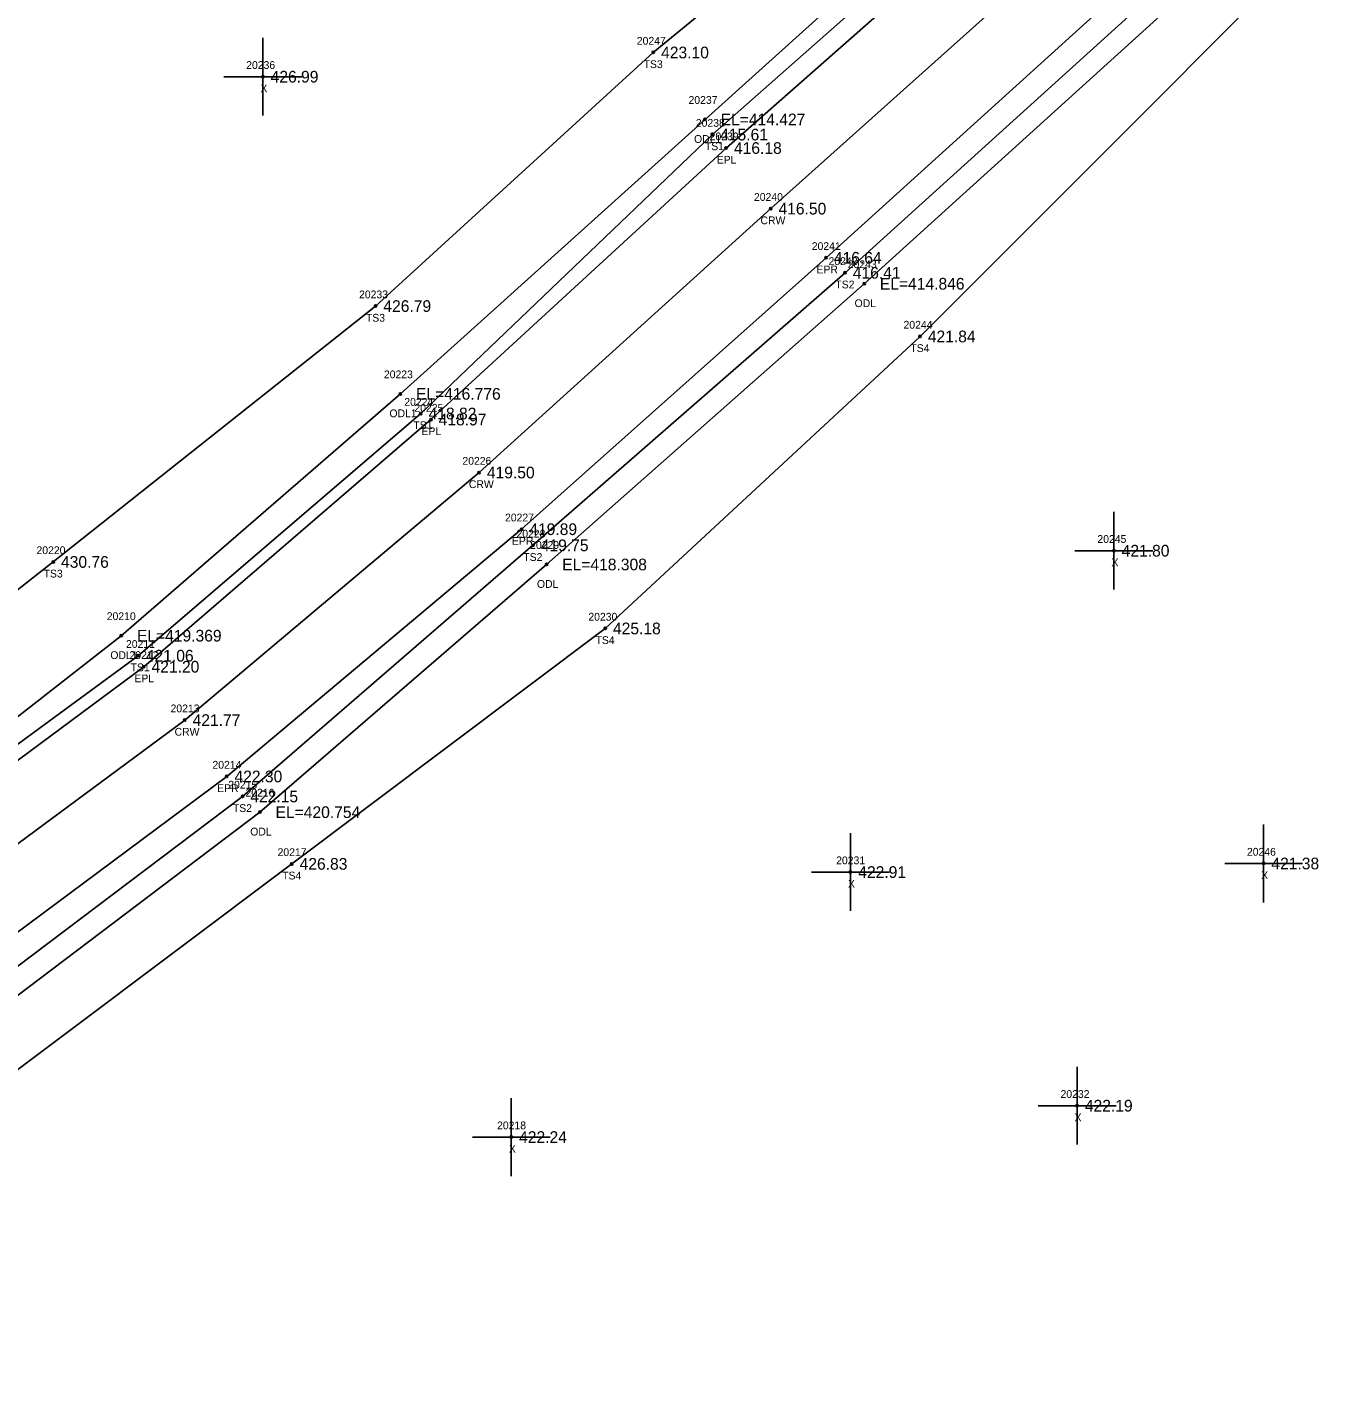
# Model space of a CAD drawing. Extents: x 2116373 to 2118139, y 979529 to 981026.
# Drawn here: x 2117006.3 to 2117175.5, y 979770.7 to 979946 of the extents above; entities that cross this region are included whole.
import ezdxf

# ---------------------------------------------------------------- set-up
doc = ezdxf.new("R2010")
doc.units = 0
for name, color, linetype in [('RD_DTM_BkLn1', 7, 'Continuous'), ('RD_DTM_BkLn2', 7, 'Continuous'), ('RD_DTM_BkLn_txCode', 7, 'Continuous'), ('RD_EX_H2O', 7, 'Continuous'), ('RD_EX_H2O_txCode', 7, 'Continuous'), ('RD_EX_Misc', 7, 'Continuous'), ('RD_EX_Misc_txCode', 7, 'Continuous'), ('RD_EX_Road', 7, 'Continuous'), ('RD_EX_Road_txCode', 7, 'Continuous'), ('RD_EX_TX_H2O_ELEV', 7, 'Continuous'), ('RD_EX_TX_Misc_ELEV', 7, 'Continuous'), ('RD_EX_TX_Road_ELEV', 7, 'Continuous'), ('RD_HC_Survey_ELEV', 7, 'Continuous'), ('RD_HC_Survey_txCode', 7, 'Continuous'), ('RD_SMD_Locator', 7, 'Continuous')]:
    doc.layers.add(name, color=color, linetype=linetype)

msp = doc.modelspace()

# ---------------------------------------------------------------- linework, layer by layer
at = {"layer": 'RD_DTM_BkLn1'}
msp.add_lwpolyline([(2116414.21, 979630.19), (2116468.62, 979643.23), (2116521.45, 979653.6), (2116618.87, 979670.38), (2116668.4, 979680.7), (2116717.3, 979694.48), (2116764.56, 979711.13), (2116810.15, 979729.38), (2116856.49, 979749.81), (2116900.74, 979773.15), (2116944.03, 979798.93), (2116982.75, 979824.6), (2117026.56, 979857.02), (2117064.34, 979888.81), (2117101.78, 979922.69), (2117176.3, 979989.4), (2117250.99, 980056.19), (2117326.56, 980126.36)], dxfattribs=at)
at = {"layer": 'RD_DTM_BkLn2'}
for points in [[(2116410.78, 979641.79), (2116465.45, 979654.97), (2116518.83, 979664.89), (2116614.96, 979683.75), (2116663.75, 979692.58), (2116713.02, 979705.22), (2116760.07, 979721.97), (2116804.88, 979741.47), (2116850.79, 979761.38), (2116894.83, 979783.88), (2116937.98, 979807.44), (2116977.39, 979833.6), (2117020.56, 979865.29), (2117056.86, 979896.38), (2117094.29, 979932.2), (2117168.14, 979997.38), (2117238.71, 980069.61), (2117312.33, 980134.21), (2117318.43, 980135.16)], [(2116408.48, 979653.74), (2116461.38, 979665.42), (2116520.7, 979678.48), (2116616.28, 979695.74), (2116661.37, 979703.79), (2116711.18, 979715.21), (2116757.77, 979732.03), (2116802.04, 979749.54), (2116847.76, 979769.63), (2116889.13, 979795.82), (2116931.32, 979820.72), (2116972.01, 979847.71), (2117009.67, 979877.33), (2117051.05, 979910.18), (2117086.71, 979942.74), (2117161.4, 980003.96), (2117222.13, 980080.24), (2117265.44, 980120.03)], [(2116417.57, 979618.2), (2116471.29, 979630.11), (2116523.91, 979640.31), (2116563.87, 979646.21), (2116622.92, 979650.9), (2116673.37, 979660.68), (2116721.38, 979672.44), (2116775.31, 979687.3), (2116820.23, 979708.52), (2116865.35, 979734.51), (2116907.21, 979760.29), (2116934.42, 979772.82), (2116951.5, 979788.78), (2116990.39, 979814.35), (2117033.97, 979847.22), (2117071.26, 979879.46), (2117111.32, 979914.45), (2117184.14, 979980.37), (2117264.18, 980040.84), (2117335.34, 980108.05), (2117336.43, 980115.6)], [(2116934.42, 979772.82), (2116956.11, 979780.15), (2116996.15, 979805.42), (2117040.3, 979838.56), (2117080.53, 979868.79), (2117120.95, 979906.28), (2117189.36, 979974.74), (2117275.31, 980029.9), (2117344.8, 980095.54)]]:
    msp.add_lwpolyline(points, dxfattribs=at)
at = {"layer": 'RD_EX_H2O'}
for points in [[(2116411.09, 979644.42), (2116463.93, 979657.73), (2116517.88, 979668.38), (2116615.09, 979686.35), (2116663.35, 979695.16), (2116711.62, 979708.91), (2116758.49, 979726.13), (2116778.25, 979736.27), (2116803.5, 979744.47), (2116849.89, 979764.23), (2116894.14, 979786.32), (2116936.31, 979809.39), (2116976.21, 979834.9), (2117018.41, 979867.86), (2117054.24, 979898.91), (2117093.35, 979934.14), (2117166.11, 979999.69), (2117224.07, 980077.92), (2117265.44, 980120.03)], [(2116934.42, 979772.82), (2116952.72, 979786.01), (2116992.31, 979812.05), (2117036.21, 979845.2), (2117073.01, 979877), (2117113.79, 979913.05), (2117185.72, 979978.24), (2117270.2, 980032.33), (2117344.8, 980095.54)]]:
    msp.add_lwpolyline(points, dxfattribs=at)
at = {"layer": 'RD_EX_Misc'}
for p, q in [((2117036.58, 979934.63), (2117036.58, 979944.63)), ((2117031.58, 979939.63), (2117041.58, 979939.63)), ((2117145.84, 979873.77), (2117145.84, 979883.77)), ((2117140.84, 979878.77), (2117150.84, 979878.77)), ((2117112.02, 979832.51), (2117112.02, 979842.51)), ((2117165.06, 979833.61), (2117165.06, 979843.61)), ((2117107.02, 979837.51), (2117117.02, 979837.51)), ((2117160.06, 979838.61), (2117170.06, 979838.61)), ((2117141.11, 979802.51), (2117141.11, 979812.51)), ((2117068.48, 979798.48), (2117068.48, 979808.48)), ((2117136.11, 979807.51), (2117146.11, 979807.51)), ((2117063.48, 979803.48), (2117073.48, 979803.48))]:
    msp.add_line(p, q, dxfattribs=at)
at = {"layer": 'RD_EX_Road'}
for points in [[(2116412.2, 979638.84), (2116468.17, 979651.36), (2116519.2, 979662.5), (2116617.24, 979678.85), (2116665.51, 979689.1), (2116714.23, 979702.46), (2116761.42, 979719.35), (2116806.99, 979737.42), (2116852.23, 979758.11), (2116896.57, 979780.91), (2116939.1, 979805.52), (2116978.46, 979832.1), (2117021.29, 979863.87), (2117058.15, 979895.61), (2117096.06, 979930.47), (2117170.14, 979995.71), (2117244.91, 980062.82), (2117320.63, 980133.49), (2117326.56, 980126.36)], [(2116416.36, 979621.21), (2116470.51, 979634.11), (2116523.97, 979644.68), (2116620.55, 979661.21), (2116670.7, 979671.96), (2116720.65, 979685.84), (2116767.66, 979702.22), (2116814.07, 979721.02), (2116860.35, 979742.3), (2116904.9, 979765.18), (2116949.06, 979791.19), (2116988.09, 979817.15), (2117031.94, 979849.78), (2117069.79, 979881.53), (2117108.89, 979916.38), (2117182.06, 979982.67), (2117257.56, 980049.29), (2117334.73, 980117.38), (2117326.56, 980126.36)]]:
    msp.add_lwpolyline(points, dxfattribs=at)
at = {"layer": 'RD_SMD_Locator'}
for centre in [(2117086.71, 979942.74), (2117036.58, 979939.63), (2117093.35, 979934.14), (2117094.29, 979932.2), (2117096.06, 979930.47), (2117101.78, 979922.69), (2117108.89, 979916.38), (2117111.32, 979914.45), (2117113.79, 979913.05), (2117051.05, 979910.18), (2117120.95, 979906.28), (2117054.24, 979898.91), (2117056.86, 979896.38), (2117058.15, 979895.61), (2117064.34, 979888.81), (2117069.79, 979881.53), (2117071.26, 979879.46), (2117009.67, 979877.33), (2117145.84, 979878.77), (2117073.01, 979877), (2117080.53, 979868.79), (2117018.41, 979867.86), (2117020.56, 979865.29), (2117021.29, 979863.87), (2117026.56, 979857.02), (2117031.94, 979849.78), (2117033.97, 979847.22), (2117036.21, 979845.2), (2117040.3, 979838.56), (2117112.02, 979837.51), (2117165.06, 979838.61), (2117141.11, 979807.51), (2117068.48, 979803.48)]:
    msp.add_circle(centre, 0.15, dxfattribs=at)

# ---------------------------------------------------------------- texts
at = {"layer": 'RD_DTM_BkLn_txCode'}
for s, p in [('20247', (2117084.59, 979943.74)), ('TS3', (2117085.46, 979940.74)), ('20238', (2117092.17, 979933.2)), ('TS1', (2117093.33, 979930.2)), ('20242', (2117109.21, 979915.45)), ('TS2', (2117110.08, 979912.45)), ('20233', (2117048.93, 979911.18)), ('TS3', (2117049.81, 979908.18)), ('20244', (2117118.83, 979907.28)), ('TS4', (2117119.71, 979904.28)), ('20224', (2117054.74, 979897.38)), ('TS1', (2117055.9, 979894.38)), ('20228', (2117069.14, 979880.46)), ('20220', (2117007.52, 979878.33)), ('TS2', (2117070.02, 979877.46)), ('TS3', (2117008.43, 979875.33)), ('20230', (2117078.37, 979869.79)), ('20211', (2117019.01, 979866.29)), ('TS4', (2117079.29, 979866.79)), ('TS1', (2117019.6, 979863.29)), ('20215', (2117032.14, 979848.22)), ('TS2', (2117032.73, 979845.22)), ('20217', (2117038.47, 979839.56)), ('TS4', (2117039.06, 979836.56))]:
    msp.add_text(s, height=1, dxfattribs=at).set_placement(p)
at = {"layer": 'RD_EX_H2O_txCode'}
for s, p in [('20237', (2117091.23, 979936.14)), ('ODL1', (2117091.94, 979931.14)), ('20243', (2117111.67, 979915.05)), ('ODL', (2117112.55, 979910.05)), ('20223', (2117052.12, 979900.91)), ('ODL1', (2117052.83, 979895.91)), ('20229', (2117070.9, 979879)), ('ODL', (2117071.77, 979874)), ('20210', (2117016.54, 979869.86)), ('ODL1', (2117017, 979864.86)), ('20216', (2117034.35, 979847.2)), ('ODL', (2117034.96, 979842.2))]:
    msp.add_text(s, height=1, dxfattribs=at).set_placement(p)
at = {"layer": 'RD_EX_Misc_txCode'}
for s, p in [('20236', (2117034.44, 979940.63)), ('X', (2117036.27, 979937.63)), ('20245', (2117143.72, 979879.77)), ('X', (2117145.53, 979876.77)), ('20246', (2117162.92, 979839.61)), ('20231', (2117110.18, 979838.51)), ('X', (2117164.75, 979836.61)), ('X', (2117111.7, 979835.51)), ('20232', (2117138.99, 979808.51)), ('20218', (2117066.65, 979804.48)), ('X', (2117140.79, 979805.51)), ('X', (2117068.17, 979801.48))]:
    msp.add_text(s, height=1, dxfattribs=at).set_placement(p)
at = {"layer": 'RD_EX_Road_txCode'}
for s, p in [('20239', (2117093.94, 979931.47)), ('EPL', (2117094.85, 979928.47)), ('20241', (2117107.05, 979917.38)), ('EPR', (2117107.66, 979914.38)), ('20225', (2117056.03, 979896.61)), ('EPL', (2117056.95, 979893.61)), ('20227', (2117067.67, 979882.53)), ('EPR', (2117068.56, 979879.53)), ('20212', (2117019.46, 979864.87)), ('EPL', (2117020.09, 979861.87)), ('20214', (2117030.11, 979850.78)), ('EPR', (2117030.71, 979847.78))]:
    msp.add_text(s, height=1, dxfattribs=at).set_placement(p)
at = {"layer": 'RD_EX_TX_H2O_ELEV'}
for s, p in [('EL=414.427', (2117095.35, 979933.39)), ('EL=414.846', (2117115.79, 979912.3)), ('EL=416.776', (2117056.24, 979898.16)), ('EL=418.308', (2117075.01, 979876.25)), ('EL=419.369', (2117020.41, 979867.11)), ('EL=420.754', (2117038.21, 979844.45))]:
    msp.add_text(s, height=1.5, dxfattribs=at).set_placement(p)
at = {"layer": 'RD_EX_TX_Misc_ELEV'}
for s, p in [('423.10', (2117087.71, 979941.99)), ('426.99', (2117037.58, 979938.88)), ('415.61', (2117095.29, 979931.45)), ('416.41', (2117112.32, 979913.7)), ('426.79', (2117052.05, 979909.43)), ('421.84', (2117121.95, 979905.53)), ('418.82', (2117057.86, 979895.63)), ('419.75', (2117072.26, 979878.71)), ('421.80', (2117146.84, 979878.02)), ('430.76', (2117010.67, 979876.58)), ('425.18', (2117081.53, 979868.04)), ('421.06', (2117021.56, 979864.54)), ('422.15', (2117034.97, 979846.47)), ('426.83', (2117041.3, 979837.81)), ('421.38', (2117166.06, 979837.86)), ('422.91', (2117113.02, 979836.76)), ('422.19', (2117142.11, 979806.76)), ('422.24', (2117069.48, 979802.73))]:
    msp.add_text(s, height=1.5, dxfattribs=at).set_placement(p)
at = {"layer": 'RD_EX_TX_Road_ELEV'}
for s, p in [('416.18', (2117097.06, 979929.72)), ('416.64', (2117109.89, 979915.63)), ('418.97', (2117059.15, 979894.86)), ('419.89', (2117070.79, 979880.78)), ('421.20', (2117022.29, 979863.12)), ('422.30', (2117032.94, 979849.03))]:
    msp.add_text(s, height=1.5, dxfattribs=at).set_placement(p)
at = {"layer": 'RD_HC_Survey_ELEV'}
for s, p in [('416.50', (2117102.78, 979921.94)), ('419.50', (2117065.34, 979888.06)), ('421.77', (2117027.56, 979856.27))]:
    msp.add_text(s, height=1.5, dxfattribs=at).set_placement(p)
at = {"layer": 'RD_HC_Survey_txCode'}
for s, p in [('20240', (2117099.63, 979923.69)), ('CRW', (2117100.47, 979920.69)), ('20226', (2117062.2, 979889.81)), ('CRW', (2117063.03, 979886.81)), ('20213', (2117024.73, 979858.02)), ('CRW', (2117025.25, 979855.02))]:
    msp.add_text(s, height=1, dxfattribs=at).set_placement(p)

doc.saveas('drawing.dxf')
